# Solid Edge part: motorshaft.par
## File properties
Author: Robert a Rhodes jr
Template: NORMENG.PAR
Last saved by: CADCIM
Revision: 3
Application: Solid Edge
Density: 0 lbm/in^3
Accuracy: 0.99
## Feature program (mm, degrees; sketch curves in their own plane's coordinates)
sketch for "unnamed Protrusion 1" plane through (0, 0, 0) normal (0, -1, 0) x-axis (1, 0, 0)
  circle centre (0, 0) radius 18.415
extrude "unnamed Protrusion 1" add finite 609.6 along -normal
sketch for "unnamed RevolvedCutout 1" plane through (0, 0, 0) normal (0, 0, 1) x-axis (1, 0, 0)
  line (18.415, 592.328) -> (18.415, 596.9)
  line (18.415, 596.9) -> (14.1403, 596.9)
  line (14.1403, 596.9) -> (14.1403, 592.328)
  line (14.1403, 592.328) -> (18.415, 592.328)
revolve "unnamed RevolvedCutout 1" cut finite 360 deg about sketch line (-1.0997, 601.5888) -> (-1.0997, 629.75)
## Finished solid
Body 1: solid body, 7 faces, 6 edges, 0 vertices.
  Faces by surface: plane 4, cylinder 3
  Edges by curve: circle 6
Bounding box of the edges (mm): 36.830 x 609.600 x 36.830, from (-18.415, 0, -18.415) to (18.415, 609.6, 18.415).
Cylindrical faces by radius (mm): R15.24 x1, R18.415 x2
Planar faces by outward normal: +y 2, -y 2
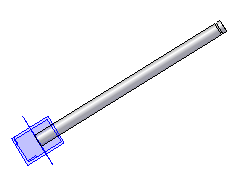
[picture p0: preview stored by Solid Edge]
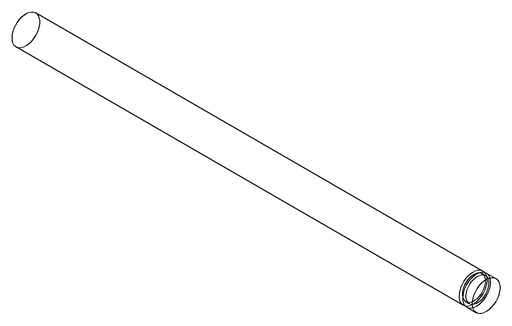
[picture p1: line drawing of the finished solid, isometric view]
